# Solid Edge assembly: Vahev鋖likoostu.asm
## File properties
Author: Türk
Template: Iso Assembly.asm
Last saved by: Türk
Revision: 9
Application: Solid Edge
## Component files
ll.par
1k_R15.par
2k_R20.par
3k_R24.par
4k2_R30.par
5k_R40.par
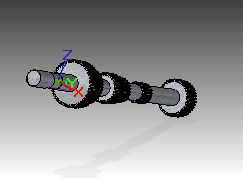
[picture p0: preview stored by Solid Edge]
